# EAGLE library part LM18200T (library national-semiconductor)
3A, 55V H-Bridge Motor Control SourcE: http://cache.national.com/ds/LM/LMD18200.pdf
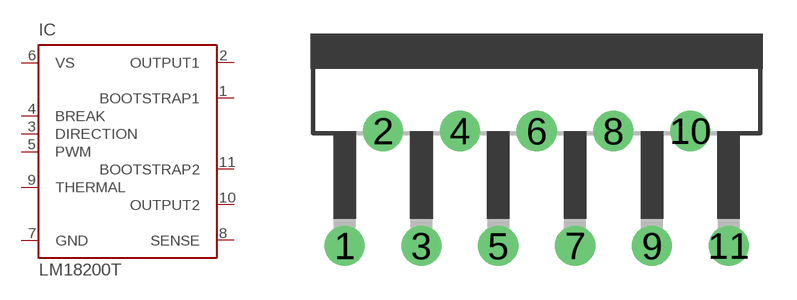
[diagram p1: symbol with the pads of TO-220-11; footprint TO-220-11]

Designator prefix IC

## LM18200T (OC_FARNELL: unknown; OC_NEWARK: unknown)  [TO-220-11]
1  BOOTSTRAP1  in
2  OUTPUT1  out
3  DIRECTION  in
4  BREAK  in
5  PWM  in
6  VS  pwr
7  GND  pwr
8  SENSE  out
9  THERMAL  out
10  OUTPUT2  out
11  BOOTSTRAP2  in

## Footprint TO-220-11 (pad centres in mm)
11-Lead TO-220 Power Package (T) NS Package Number TA11B Source: http://cache.national.com/ds/LM/LMD18200.pdf
drill 1.1 pad 1.778 round: 1 -8.5,-9.37; 2 -6.8,-4.29; 3 -5.1,-9.37; 4 -3.4,-4.29; 5 -1.7,-9.37; 6 0,-4.29; 7 1.7,-9.37; 8 3.4,-4.29; 9 5.1,-9.37; 10 6.8,-4.29; 11 8.5,-9.37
